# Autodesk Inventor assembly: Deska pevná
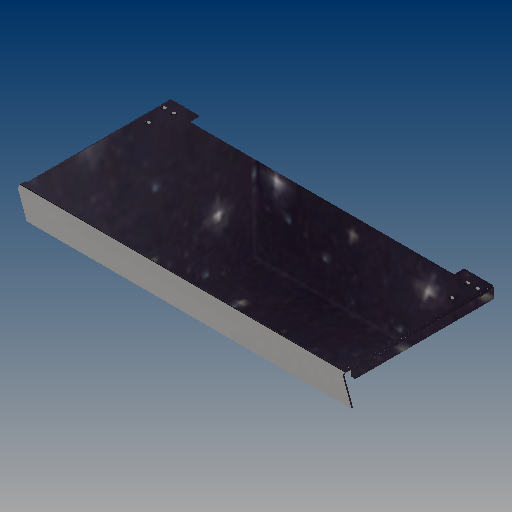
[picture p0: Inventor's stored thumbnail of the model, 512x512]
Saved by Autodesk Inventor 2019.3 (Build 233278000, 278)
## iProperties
Created: 2019-02
Part Number: Deska pevná
Material: Všeobecné
Document SubType Name: Assembly
Designer: B-hon
Author: B-hon
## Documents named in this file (4)
- C:\Users\B-hon\OneDrive\Plocha\Bakalářka22\Deska pevná\Deska pevná.iam
- C:\Users\B-hon\OneDrive\Plocha\Bakalářka22\Deska pevná\Plech deskyp.ipt
- C:\Users\B-hon\OneDrive\Plocha\Bakalářka22\Deska pevná\Výztuha1p.ipt
- C:\Users\B-hon\OneDrive\Plocha\Bakalářka22\Deska pevná\Výztuha2p.ipt
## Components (3 placed, 3 different names)
1. Plech deskyp:1 — Vložit:1, Vložit:2, Vložit:3, Vložit:4
2. Výztuha1p:1 — Vložit:3, Vložit:4
3. Výztuha2p:1 — Vložit:1, Vložit:2
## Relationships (4: Insert 4)
- Vložit:1 [Insert]: Plech deskyp:1 ↔ Výztuha2p:1
- Vložit:2 [Insert]: Plech deskyp:1 ↔ Výztuha2p:1
- Vložit:3 [Insert]: Plech deskyp:1 ↔ Výztuha1p:1
- Vložit:4 [Insert]: Plech deskyp:1 ↔ Výztuha1p:1
